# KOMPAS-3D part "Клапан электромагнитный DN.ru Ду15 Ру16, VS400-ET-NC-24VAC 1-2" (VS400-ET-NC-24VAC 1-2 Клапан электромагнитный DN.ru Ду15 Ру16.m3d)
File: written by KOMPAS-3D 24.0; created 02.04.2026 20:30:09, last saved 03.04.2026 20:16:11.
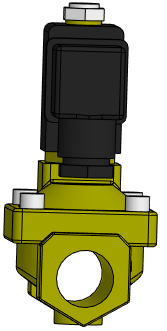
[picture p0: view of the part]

Document properties: Автор: artio; Полное имя файла: C:\Users\artio\OneDrive\Рабочий стол\Клапан электромагнитный DN.ru\VS400-ET-NC\VS400-ET-NC-24VAC 1-2 Клапан электромагнитный DN.ru Ду15 Ру16.m3d

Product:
- Body: Тело 1  | qty 1
    Масса: 1.030062
- Part/product: Клапан электромагнитный DN.ru Ду15 Ру16  | designation VS400-ET-NC-24VAC 1-2
    Масса: 0.759
    Раздел спецификации: Прочие изделия
    Примечание: D130-05629
    additional columns: ef56311e-7521-43dc-8291-0e6108b3d81d; VS400-ET-NC-220VAC 1-2; artio; c; Шероховатость не задана; Да

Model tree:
1. Операция без истории:1

Expressions: VS400-ET-NC-24VAC 1-2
